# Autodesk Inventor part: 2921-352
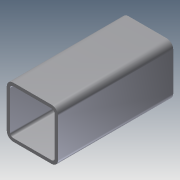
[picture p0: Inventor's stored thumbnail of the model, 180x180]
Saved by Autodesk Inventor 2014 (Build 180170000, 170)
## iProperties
Company: NHTSA/VRTC
Created: 2012-08
Part Number: 2921-352
Material: Generic
Document SubType Name: Modeling
Designer: Mioke Vanvoorhis
Density: 1 g/cm^3
Mass: 65.6077 g
Surface Area: 428.475 cm^2
Volume: 65.6077 cm^3
Project: CHILD SIDE IMPACT SLED
Description: LOWER ANCHOR VERTICAL TUBE
Stock Number: T.S. 2" x 2" x 1/8" x 114.3mm (4.5")
Appearance: Default
Author: Dave Walker
Title: Lower Anchor Vertical Tube
Subject: Child Side Impact Sled
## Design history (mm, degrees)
sketch "Sketch1"
  geometry: L1 (6.35, 0)-(44.45, 0); L2 (50.8, 6.35)-(50.8, 44.45); L3 (44.45, 50.8)-(6.35, 50.8); L4 (0, 44.45)-(0, 6.35); L5 (6.35, 47.653)-(44.45, 47.653); L6 (47.653, 44.45)-(47.653, 6.35); L7 (44.45, 3.147)-(6.35, 3.147); L8 (3.147, 6.35)-(3.147, 44.45); A1 r 6.35 centre (6.35, 44.45) between (6.35, 50.8) and (0, 44.45); A2 r 6.35 centre (6.35, 6.35) between (0, 6.35) and (6.35, 0); A3 r 6.35 centre (44.45, 6.35) between (44.45, 0) and (50.8, 6.35); A4 r 6.35 centre (44.45, 44.45) between (50.8, 44.45) and (44.45, 50.8); A5 r 3.203 centre (44.45, 44.45) between (47.653, 44.45) and (44.45, 47.653); A6 r 3.203 centre (44.45, 6.35) between (44.45, 3.147) and (47.653, 6.35); A7 r 3.203 centre (6.35, 6.35) between (3.147, 6.35) and (6.35, 3.147); A8 r 3.203 centre (6.35, 44.45) between (6.35, 47.653) and (3.147, 44.45); 4 further points
  constraints: 16 end point, 16 point on circle, 8 centre point, 8 point on line, 8 tangent, 4 parallel, 3 equal radius, 2 perpendicular, 1 horizontal, 7 other
  dimensions: "d0" = 50.8 distance of point (0, 50.8) point (50.8, 50.8); "d1" = 50.8 distance of point (50.8, 50.8) point (50.8, 0); "d2" = 6.35 radius of A1
extrude "Extrusion1" new body sketch "Sketch1" distance "d3" = 114.3; taper "d4" = 0 deg
body "Solid1"
